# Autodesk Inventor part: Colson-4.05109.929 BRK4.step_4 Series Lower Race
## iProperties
Created: 2010-10
Part Number: Colson-4.05109.929 BRK4.step_4 Series Lower Race
Document SubType Name: Modeling
Designer: Administrator
Density: 7.85 g/cm^3
Material: Steel
Mass: 93.6004 g
Surface Area: 67.2485 cm^2
Volume: 11.9236 cm^3
Author: Administrator
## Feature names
1. Base1
